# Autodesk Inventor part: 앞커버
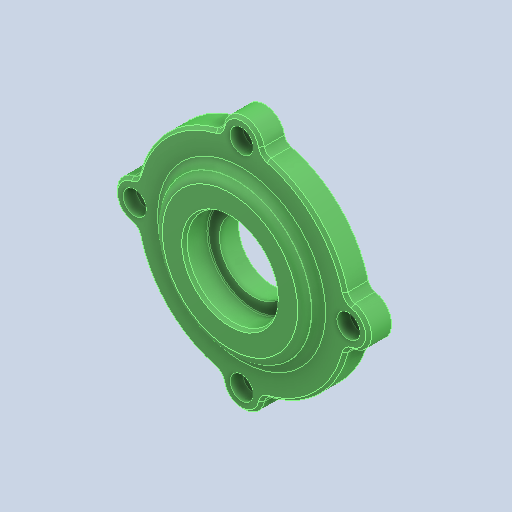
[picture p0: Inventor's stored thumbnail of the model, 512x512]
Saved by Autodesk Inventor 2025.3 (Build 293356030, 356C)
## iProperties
Created: 2025-08
Part Number: 앞커버
Material: 알루미늄 6061
Document SubType Name: Modeling
Designer: user
Density: 2.71 g/cm^3
Appearance: 기본값
Company: 한국ATC센터
Sending System: Autodesk Inventor 2026
Preprocessor: ST-DEVELOPER v20.1
Author: jhkim
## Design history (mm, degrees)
sketch "스케치1"
  geometry: 1 further point
  constraints: 1 other
feature "솔리드1"
node "솔리드2"
